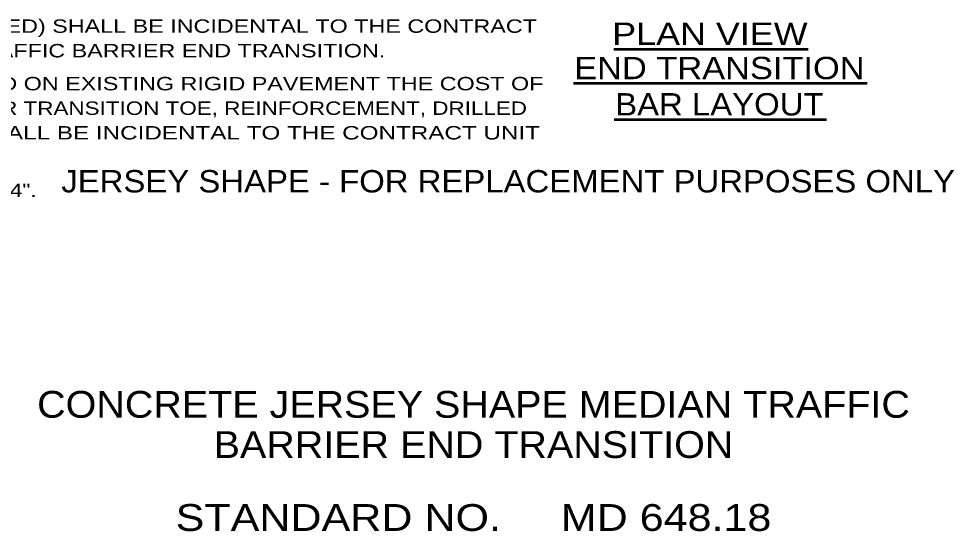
# Model space of a CAD drawing. Extents: x -11.7 to -4.5, y 8.6 to 18.8.
# Drawn here: x -8.704 to -4.52, y 8.593 to 10.888 of the extents above; entities that cross this region are included whole.
import ezdxf
from ezdxf.enums import TextEntityAlignment as Align

# ---------------------------------------------------------------- set-up
doc = ezdxf.new("R2010")
doc.units = 0
doc.header["$LTSCALE"] = 0.024
doc.layers.add('12', color=7, linetype='Continuous', lineweight=53)
doc.layers.add('13', color=7, linetype='Continuous', lineweight=53)

msp = doc.modelspace()

# ---------------------------------------------------------------- linework, layer by layer
at = {"layer": '12'}
for p, q in [((-6.04233, 10.75167), (-5.17367, 10.75167)), ((-6.22217, 10.5985), (-4.90867, 10.5985)), ((-6.04017, 10.436), (-5.09067, 10.436))]:
    msp.add_line(p, q, dxfattribs=at)

# ---------------------------------------------------------------- texts
for s, width, p in [('PLAN VIEW', 1.2, (-5.61258, 10.77025)), ('END TRANSITION', 1.15, (-5.57029, 10.617)), ('BAR LAYOUT', 1.1, (-5.57033, 10.4545))]:
    msp.add_text(s, height=0.1, dxfattribs=dict(at, width=width)).set_placement(p, align=Align.CENTER)
at = {"layer": '12', "width": 1.1}
msp.add_text('JERSEY SHAPE - FOR REPLACEMENT PURPOSES ONLY', height=0.1, dxfattribs=at).set_placement((-4.51642, 10.11017), align=Align.RIGHT)
at = {"layer": '13'}
for s, width, p in [('5. COST OF THE CONCRETE BARRIER FOOTER (IF REQUIRED) SHALL BE INCIDENTAL TO THE CONTRACT', 1.3, (-11.74192, 10.8245)), ('   UNIT PRICE PER EACH FOR THE CONCRETE MEDIAN TRAFFIC BARRIER END TRANSITION.', 1.3, (-11.74192, 10.7145)), ('6. WHEN THE BARRIER END TRANSITION IS CONSTRUCTED ON EXISTING RIGID PAVEMENT THE COST OF ', 1.3, (-11.74192, 10.56708)), ('   ROUGHENING THE PAVEMENT SURFACE, EXCAVATION FOR TRANSITION TOE, REINFORCEMENT, DRILLED ', 1.25, (-11.74192, 10.45708)), ('   HOLES, GROUT, LABOR, TOOLS, EQUIPMENT, ETC., SHALL BE INCIDENTAL TO THE CONTRACT UNIT', 1.35, (-11.74192, 10.34708)), ('7. TOLERANCES IN DIMENSIONS SHOWN SHALL BE WITHIN 1/4".', 1.25, (-11.74192, 10.08967))]:
    msp.add_text(s, height=0.06001, dxfattribs=dict(at, width=width)).set_placement(p)
for s, width, p in [('CONCRETE JERSEY SHAPE MEDIAN TRAFFIC', 1.1, (-6.66996, 9.1015)), ('BARRIER END TRANSITION', 1.1, (-6.66996, 8.9215)), ('STANDARD NO.     MD 648.18', 1.2, (-6.66988, 8.595))]:
    msp.add_text(s, height=0.12, dxfattribs=dict(at, width=width)).set_placement(p, align=Align.CENTER)

doc.saveas('drawing.dxf')
